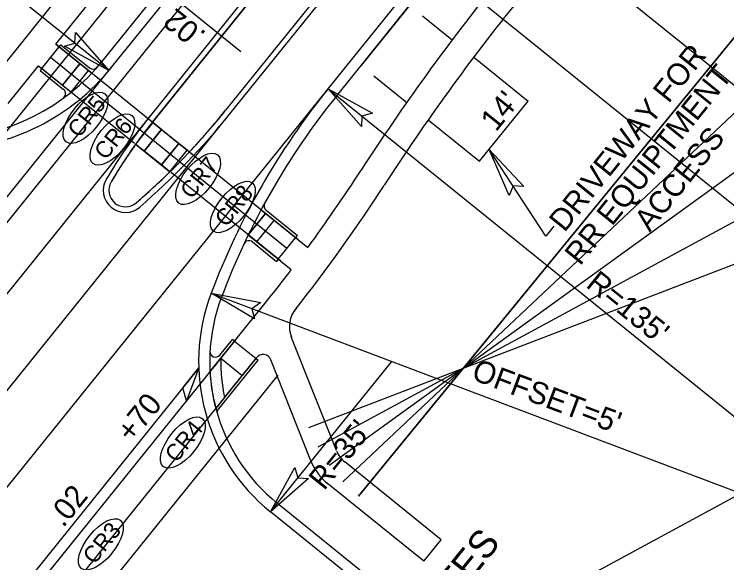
# Model space of a CAD drawing. Extents: x 1486489 to 1490134, y 497089 to 500876.
# Drawn here: x 1488715.1 to 1488844.3, y 499048.4 to 499147.7 of the extents above; entities that cross this region are included whole.
import ezdxf

# ---------------------------------------------------------------- set-up
doc = ezdxf.new("R2010")
doc.units = 0
for name, color, linetype in [('DEV PRELIMINARY STAMP CELL', 7, 'Continuous'), ('Gray Area Fill Shapes', 7, 'Continuous'), ('Pattern 5', 7, 'Continuous'), ('Prop Conc 5in Monolithic Surface Mount Island', 7, 'Continuous'), ('Prop Conc Drive Radius Type', 7, 'Continuous'), ('Prop DSN Text', 7, 'Continuous'), ('Prop Guardrail Anchor Unit CELL', 7, 'Continuous'), ('Prop Horizontal Alignment Station Label', 7, 'Continuous'), ('Prop North Arrow NAD83 for Plan Sheets CELL', 7, 'Continuous'), ('Prop Text', 7, 'Continuous'), ('Prop WCC CELL', 7, 'Continuous'), ('Scratch_Level_0', 7, 'Continuous'), ('Scratch_Level_5', 7, 'Continuous'), ('Sheet Block Title CELL', 7, 'Continuous'), ('Sheet Border Standard 30in CELL', 7, 'Continuous'), ('Sheet Cutting Line CELL', 7, 'Continuous'), ('Sheet Plan CELL', 7, 'Continuous'), ('Sheet Plot Border Outside CELL', 7, 'Continuous'), ('Sheet Sticker Exception Certification CELL', 7, 'Continuous'), ('Sheet Title CELL', 7, 'Continuous')]:
    doc.layers.add(name, color=color, linetype=linetype)

msp = doc.modelspace()

# ---------------------------------------------------------------- linework, layer by layer
at = {"layer": 'DEV PRELIMINARY STAMP CELL'}
for p, q in [((1488756.24, 499140.92), (1488743.4, 499151.27)), ((1488748.59, 499083.64), (1488718.98, 499046.92))]:
    msp.add_line(p, q, dxfattribs=at)
msp.add_lwpolyline([(1488748.59, 499083.64), (1488746.38, 499077.71), (1488745.69, 499080.04)], close=True, dxfattribs=at)
at = {"layer": 'Pattern 5'}
for p, q in [((1488727.05, 499138.76), (1488723.91, 499134.87)), ((1488728.61, 499137.51), (1488727.05, 499138.76)), ((1488725.47, 499133.61), (1488728.61, 499137.51)), ((1488723.91, 499134.87), (1488725.47, 499133.61)), ((1488740.29, 499128.08), (1488737.15, 499124.19)), ((1488741.85, 499126.83), (1488740.29, 499128.08)), ((1488738.71, 499122.94), (1488741.85, 499126.83)), ((1488737.15, 499124.19), (1488738.71, 499122.94)), ((1488744.95, 499124.33), (1488741.81, 499120.44)), ((1488746.51, 499123.07), (1488744.95, 499124.33)), ((1488743.37, 499119.18), (1488746.51, 499123.07)), ((1488741.81, 499120.44), (1488743.37, 499119.18)), ((1488760.7, 499111.63), (1488757.56, 499107.73)), ((1488762.26, 499110.37), (1488760.7, 499111.63)), ((1488759.12, 499106.48), (1488762.26, 499110.37)), ((1488757.56, 499107.73), (1488759.12, 499106.48)), ((1488750.62, 499082.97), (1488752.58, 499085.4)), ((1488751.81, 499084.16), (1488751.81, 499084.16)), ((1488752.05, 499084.45), (1488752.05, 499084.45)), ((1488752.28, 499084.74), (1488752.28, 499084.74)), ((1488752.46, 499084.36), (1488752.46, 499084.36)), ((1488752.52, 499085.03), (1488752.52, 499085.03)), ((1488750.87, 499082.99), (1488750.87, 499082.99)), ((1488751.1, 499083.28), (1488751.1, 499083.28)), ((1488751.28, 499082.9), (1488751.28, 499082.9)), ((1488751.34, 499083.57), (1488751.34, 499083.57)), ((1488751.51, 499083.19), (1488751.51, 499083.19)), ((1488751.57, 499083.87), (1488751.57, 499083.87)), ((1488751.69, 499082.81), (1488751.69, 499082.81)), ((1488751.75, 499083.48), (1488751.75, 499083.48)), ((1488751.92, 499083.1), (1488751.92, 499083.1)), ((1488751.98, 499083.78), (1488751.98, 499083.78)), ((1488752.16, 499083.39), (1488752.16, 499083.39)), ((1488752.22, 499084.07), (1488752.22, 499084.07)), ((1488752.33, 499083.01), (1488752.33, 499083.01)), ((1488752.39, 499083.69), (1488752.39, 499083.69)), ((1488752.57, 499083.31), (1488752.57, 499083.31)), ((1488750.75, 499081.64), (1488750.75, 499081.64)), ((1488750.81, 499082.32), (1488750.81, 499082.32)), ((1488750.98, 499081.93), (1488750.98, 499081.93)), ((1488751.04, 499082.61), (1488751.04, 499082.61)), ((1488751.16, 499081.55), (1488751.16, 499081.55)), ((1488751.22, 499082.23), (1488751.22, 499082.23)), ((1488751.39, 499081.85), (1488751.39, 499081.85)), ((1488751.45, 499082.52), (1488751.45, 499082.52)), ((1488751.63, 499082.14), (1488751.63, 499082.14)), ((1488751.8, 499081.76), (1488751.8, 499081.76)), ((1488751.86, 499082.43), (1488751.86, 499082.43)), ((1488752.04, 499082.05), (1488752.04, 499082.05)), ((1488752.1, 499082.72), (1488752.1, 499082.72)), ((1488752.21, 499081.67), (1488752.21, 499081.67)), ((1488752.27, 499082.34), (1488752.27, 499082.34)), ((1488752.45, 499081.96), (1488752.45, 499081.96)), ((1488752.51, 499082.63), (1488752.51, 499082.63)), ((1488752.62, 499081.58), (1488752.62, 499081.58)), ((1488750.86, 499080.59), (1488750.86, 499080.59)), ((1488750.92, 499081.26), (1488750.92, 499081.26)), ((1488751.03, 499080.21), (1488751.03, 499080.21)), ((1488751.09, 499080.88), (1488751.09, 499080.88)), ((1488751.27, 499080.5), (1488751.27, 499080.5)), ((1488751.33, 499081.17), (1488751.33, 499081.17)), ((1488751.5, 499080.79), (1488751.5, 499080.79)), ((1488751.57, 499081.46), (1488751.57, 499081.46)), ((1488751.68, 499080.41), (1488751.68, 499080.41)), ((1488751.74, 499081.08), (1488751.74, 499081.08)), ((1488751.91, 499080.7), (1488751.91, 499080.7)), ((1488751.97, 499081.37), (1488751.97, 499081.37)), ((1488752.09, 499080.32), (1488752.09, 499080.32)), ((1488752.15, 499080.99), (1488752.15, 499080.99)), ((1488752.32, 499080.61), (1488752.32, 499080.61)), ((1488752.38, 499081.29), (1488752.38, 499081.29)), ((1488752.5, 499080.23), (1488752.5, 499080.23)), ((1488752.56, 499080.9), (1488752.56, 499080.9)), ((1488752.73, 499080.52), (1488752.73, 499080.52)), ((1488751.15, 499079.15), (1488751.15, 499079.15)), ((1488751.21, 499079.83), (1488751.21, 499079.83)), ((1488751.38, 499079.44), (1488751.38, 499079.44)), ((1488751.44, 499080.12), (1488751.44, 499080.12)), ((1488751.56, 499079.06), (1488751.56, 499079.06)), ((1488751.62, 499079.74), (1488751.62, 499079.74)), ((1488751.79, 499079.35), (1488751.79, 499079.35)), ((1488751.85, 499080.03), (1488751.85, 499080.03)), ((1488751.97, 499078.97), (1488751.97, 499078.97)), ((1488752.03, 499079.65), (1488752.03, 499079.65)), ((1488752.2, 499079.27), (1488752.2, 499079.27)), ((1488752.26, 499079.94), (1488752.26, 499079.94)), ((1488752.44, 499079.56), (1488752.44, 499079.56)), ((1488752.61, 499079.18), (1488752.61, 499079.18)), ((1488752.67, 499079.85), (1488752.67, 499079.85)), ((1488752.85, 499079.47), (1488752.85, 499079.47)), ((1488752.91, 499080.14), (1488752.91, 499080.14)), ((1488753.02, 499079.09), (1488753.02, 499079.09)), ((1488751.26, 499078.1), (1488751.26, 499078.1)), ((1488751.32, 499078.77), (1488751.32, 499078.77)), ((1488751.43, 499077.72), (1488751.43, 499077.72)), ((1488751.49, 499078.39), (1488751.49, 499078.39)), ((1488751.67, 499078.01), (1488751.67, 499078.01)), ((1488753.26, 499078.28), (1488751.68, 499076.32)), ((1488751.73, 499078.68), (1488751.73, 499078.68)), ((1488751.84, 499077.63), (1488751.84, 499077.63)), ((1488751.9, 499078.3), (1488751.9, 499078.3)), ((1488752.08, 499077.92), (1488752.08, 499077.92)), ((1488752.14, 499078.59), (1488752.14, 499078.59)), ((1488752.31, 499078.21), (1488752.31, 499078.21)), ((1488752.38, 499078.88), (1488752.38, 499078.88)), ((1488752.49, 499077.83), (1488752.49, 499077.83)), ((1488752.55, 499078.5), (1488752.55, 499078.5)), ((1488752.72, 499078.12), (1488752.72, 499078.12)), ((1488752.78, 499078.79), (1488752.78, 499078.79)), ((1488752.96, 499078.41), (1488752.96, 499078.41)), ((1488751.61, 499077.34), (1488751.61, 499077.34)), ((1488751.78, 499076.95), (1488751.78, 499076.95)), ((1488752.02, 499077.25), (1488752.02, 499077.25)), ((1488752.25, 499077.54), (1488752.25, 499077.54))]:
    msp.add_line(p, q, dxfattribs=at)
for radius, start, end in [(31, 178.9, 192.1429), (33, 183.1773, 194.8995)]:
    msp.add_arc((1488783.57, 499084.8), radius, start, end, dxfattribs=at)
at = {"layer": 'Prop Conc 5in Monolithic Surface Mount Island'}
for p, q in [((1488740.18, 499128.17), (1488785.51, 499184.38)), ((1488785.51, 499184.38), (1488740.18, 499128.17)), ((1488753.47, 499130.31), (1488792.52, 499178.73)), ((1488753.47, 499130.31), (1488792.52, 499178.73)), ((1488738.71, 499122.94), (1488737.15, 499124.19)), ((1488744.95, 499124.33), (1488746.51, 499123.07)), ((1488741.81, 499120.44), (1488738.71, 499122.94)), ((1488746.51, 499123.07), (1488746.89, 499122.77)), ((1488743.37, 499119.18), (1488741.81, 499120.44))]:
    msp.add_line(p, q, dxfattribs=at)
msp.add_lwpolyline([(1488740.18, 499128.17), (1488740.29, 499128.08), (1488741.85, 499126.83), (1488744.95, 499124.33)], dxfattribs=at)
for centre, radius, start, end in [((1488653.05, 499211.29), 129, 310.743, 321.1156), ((1488653.05, 499211.29), 129, 316.6697, 321.1156), ((1488809.46, 499072.3), 89, 141.1156, 149.5986), ((1488809.46, 499072.3), 89, 144.3362, 149.5986), ((1488653.05, 499211.29), 129, 310.743, 314.4382), ((1488735.29, 499115.82), 3, 149.5986, 310.743), ((1488735.29, 499115.82), 3, 149.5986, 310.743)]:
    msp.add_arc(centre, radius, start, end, dxfattribs=at)
at = {"layer": 'Prop Conc Drive Radius Type'}
msp.add_line((1488786.78, 499149.32), (1488778, 499138.42), dxfattribs=at)
at = {"layer": 'Prop DSN Text'}
msp.add_line((1488566.47, 498943.86), (1488817.57, 499255.22), dxfattribs=at)
at = {"layer": 'Prop Horizontal Alignment Station Label'}
for p, q in [((1488710.38, 499134.95), (1488753.3, 499188.25)), ((1488722.67, 499142.3), (1488757.19, 499185.11)), ((1488722.67, 499142.3), (1488729.19, 499137.04)), ((1488720.14, 499137.91), (1488723.28, 499141.8)), ((1488714.03, 499131.55), (1488719.53, 499138.4)), ((1488719.53, 499138.4), (1488725.47, 499133.61)), ((1488723.91, 499134.87), (1488727.05, 499138.76)), ((1488725.47, 499133.61), (1488728.61, 499137.51)), ((1488740.29, 499128.09), (1488737.15, 499124.19)), ((1488740.18, 499128.17), (1488746.89, 499122.77)), ((1488741.85, 499126.83), (1488738.71, 499122.94)), ((1488737.15, 499124.19), (1488743.37, 499119.18)), ((1488741.81, 499120.44), (1488744.95, 499124.33)), ((1488743.37, 499119.18), (1488746.51, 499123.07)), ((1488757.56, 499107.73), (1488760.7, 499111.63)), ((1488759.89, 499112.28), (1488768.35, 499105.45)), ((1488759.12, 499106.48), (1488762.26, 499110.37)), ((1488757.56, 499107.73), (1488765.36, 499101.45)), ((1488763.01, 499103.34), (1488766.15, 499107.23)), ((1488750.62, 499082.97), (1488760.09, 499094.72)), ((1488773.56, 499068.66), (1488765.37, 499089.29)), ((1488755.09, 499088.51), (1488758.98, 499085.37)), ((1488752.58, 499085.4), (1488756.47, 499082.26)), ((1488753.26, 499078.28), (1488759.07, 499085.48)), ((1488768.91, 499066.82), (1488761.64, 499085.14)), ((1488792.52, 499052.53), (1488775.06, 499066.61)), ((1488789.38, 499048.64), (1488771.93, 499062.72)), ((1488789.38, 499048.64), (1488792.52, 499052.53))]:
    msp.add_line(p, q, dxfattribs=at)
for centre, radius, start, end in [((1489117.85, 498899.16), 405, 141.1156, 147.049), ((1489117.85, 498899.16), 400, 141.1156, 147.049), ((1488530.46, 499279.9), 295, 323.7475, 327.049), ((1488530.46, 499279.9), 300, 321.7531, 327.049), ((1488530.46, 499279.9), 295, 321.1156, 322.7757), ((1488770.02, 499091.14), 5, 139.2751, 201.6281), ((1488783.57, 499084.8), 31, 178.9, 192.1429), ((1488760.26, 499084.57), 1.5, 22.2994, 142.2924), ((1488778.2, 499070.5), 5, 201.6281, 231.1156), ((1488778.2, 499070.5), 10, 201.6281, 231.1156)]:
    msp.add_arc(centre, radius, start, end, dxfattribs=at)
at = {"layer": 'Prop North Arrow NAD83 for Plan Sheets CELL'}
for p, q in [((1488723.28, 499141.8), (1488723.59, 499142.19)), ((1488723.59, 499142.19), (1488728.79, 499138)), ((1488720.14, 499137.91), (1488719.83, 499137.52)), ((1488719.83, 499137.52), (1488724.07, 499134.1)), ((1488760.78, 499112.21), (1488766.46, 499107.62)), ((1488766.15, 499107.23), (1488766.46, 499107.62)), ((1488758.32, 499106.48), (1488762.7, 499102.95)), ((1488763.01, 499103.34), (1488762.7, 499102.95)), ((1488752.4, 499085.97), (1488754.7, 499088.82)), ((1488755.09, 499088.51), (1488754.7, 499088.82)), ((1488758.98, 499085.37), (1488759.37, 499085.06)), ((1488752.01, 499075.93), (1488759.37, 499085.06))]:
    msp.add_line(p, q, dxfattribs=at)
for centre, radius, start, end in [((1488729.42, 499138.78), 1, 231.1221, 318.6886), ((1488723.45, 499133.32), 1, 306.1294, 51.1156), ((1488761.41, 499112.98), 1, 151.2388, 231.1156), ((1488757.7, 499105.7), 1, 51.1156, 154.7881), ((1488751.62, 499086.6), 1, 176.7747, 321.1156), ((1488752.4, 499075.61), 0.5, 141.1156, 196.4245)]:
    msp.add_arc(centre, radius, start, end, dxfattribs=at)
at = {"layer": 'Prop Text'}
for p, q in [((1489031.06, 499369.78), (1488777.53, 499060.39)), ((1488774.7, 499063.04), (1489066.03, 499337.13)), ((1488740.1, 499128.24), (1488722.67, 499142.3)), ((1488719.75, 499138.23), (1488736.96, 499124.35)), ((1488766.54, 499106.92), (1488746.7, 499122.92)), ((1488763.4, 499103.03), (1488743.56, 499119.02)), ((1488755.33, 499088.81), (1488715.25, 499039.11)), ((1488723.04, 499032.83), (1488762.97, 499082.34))]:
    msp.add_line(p, q, dxfattribs=at)
at = {"layer": 'Prop WCC CELL'}
for centre in [(1488728.06, 499128.95), (1488732.94, 499125.01), (1488748.47, 499117.88), (1488754.77, 499112.8), (1488745.7, 499070.12), (1488730.84, 499051.69)]:
    msp.add_ellipse(centre, major_axis=(3.52, 4.36), ratio=0.462467, dxfattribs=at)
at = {"layer": 'Scratch_Level_0'}
for p, q in [((1488732.3, 499137.52), (1488701.17, 499162.63)), ((1488764.58, 499105.29), (1488721.71, 499139.86)), ((1488772.04, 499134.22), (1488877.12, 499049.47)), ((1488750.83, 499097.17), (1488877.12, 499049.47)), ((1488719.04, 499035.84), (1488758.98, 499085.37)), ((1488761.6, 499057.56), (1488783.57, 499084.8))]:
    msp.add_line(p, q, dxfattribs=at)
for points in [[(1488726.27, 499144.38), (1488732.3, 499137.52), (1488724.26, 499141.96), (1488726.15, 499142.48)], [(1488778.07, 499127.36), (1488772.04, 499134.22), (1488780.08, 499129.78), (1488778.18, 499129.26)], [(1488758.7, 499092.54), (1488750.83, 499097.17), (1488759.86, 499095.47), (1488758.22, 499094.38)], [(1488768.46, 499063.59), (1488761.6, 499057.56), (1488766.03, 499065.61), (1488766.56, 499063.71)]]:
    msp.add_lwpolyline(points, close=True, dxfattribs=at)
at = {"layer": 'Scratch_Level_5'}
for p, q in [((1488730.75, 499138.77), (1488778.25, 499197.68)), ((1488773.59, 499132.96), (1488807.05, 499174.45)), ((1488784.04, 499042.03), (1488762.85, 499059.11))]:
    msp.add_line(p, q, dxfattribs=at)
for centre, radius, start, end in [((1488701.63, 499163.2), 38, 222.6475, 321.1156), ((1488877.12, 499049.47), 133, 141.1156, 159.3105), ((1488783.57, 499084.8), 33, 159.3105, 231.1156)]:
    msp.add_arc(centre, radius, start, end, dxfattribs=at)
at = {"layer": 'Sheet Block Title CELL'}
for p, q in [((1488646.37, 499030.96), (1488732.3, 499137.52)), ((1488690.38, 499032.96), (1488772.04, 499134.22)), ((1488656.94, 499009.02), (1488754.24, 499129.68)), ((1488648.38, 499015.93), (1488739.4, 499128.8))]:
    msp.add_line(p, q, dxfattribs=at)
at = {"layer": 'Sheet Border Standard 30in CELL'}
for p, q in [((1488777.53, 499060.39), (1489031.06, 499369.78)), ((1489066.03, 499337.13), (1488774.7, 499063.04)), ((1488772.23, 499066.03), (1489096.5, 499300.23)), ((1489121.95, 499259.71), (1488770.16, 499069.32)), ((1489140.33, 499219.78), (1488788.55, 499029.37)), ((1488768.54, 499072.84), (1489141.95, 499216.25))]:
    msp.add_line(p, q, dxfattribs=at)
at = {"layer": 'Sheet Cutting Line CELL'}
for p, q in [((1488811.53, 499107.52), (1488801.22, 499123.23)), ((1488812.97, 499109.31), (1488811.53, 499107.52))]:
    msp.add_line(p, q, dxfattribs=at)
at = {"layer": 'Sheet Plan CELL'}
for p, q in [((1488632.83, 499306.48), (1488944.2, 499055.38)), ((1488933.52, 499042.15), (1488622.16, 499293.25)), ((1488574.59, 498937.3), (1488825.69, 499248.67))]:
    msp.add_line(p, q, dxfattribs=at)
at = {"layer": 'Sheet Plot Border Outside CELL'}
msp.add_lwpolyline([(1488804.86, 499114.86), (1488801.22, 499123.23), (1488807.52, 499116.54), (1488805.56, 499116.63)], close=True, dxfattribs=at)
at = {"layer": 'Sheet Sticker Exception Certification CELL'}
for p, q in [((1488732.3, 499137.52), (1488887.78, 499330.31)), ((1488772.04, 499134.22), (1488829.46, 499205.43)), ((1488739.4, 499128.8), (1488784.74, 499185.01)), ((1488754.24, 499129.68), (1488793.3, 499178.11)), ((1488789.12, 499147.44), (1488794.54, 499143.07)), ((1488798.43, 499139.93), (1488808.28, 499131.99)), ((1488780.33, 499136.54), (1488786.29, 499131.73)), ((1488799.49, 499121.09), (1488808.28, 499131.99)), ((1488790.19, 499128.59), (1488799.49, 499121.09)), ((1488782.79, 499040.47), (1488761.6, 499057.56))]:
    msp.add_line(p, q, dxfattribs=at)
for centre, radius, start, end in [((1488701.63, 499163.2), 40, 222.6475, 321.1156), ((1488877.12, 499049.47), 135, 141.1156, 159.3105), ((1488653.05, 499211.29), 130, 310.743, 321.1156), ((1488809.46, 499072.3), 90, 141.1156, 149.5986), ((1488735.29, 499115.82), 4, 149.5986, 310.743), ((1488783.57, 499084.8), 35, 159.3105, 231.1156)]:
    msp.add_arc(centre, radius, start, end, dxfattribs=at)

# ---------------------------------------------------------------- texts
at = {"layer": 'Gray Area Fill Shapes'}
for s, rotation, p in [('.02', 141.1755, (1488750.13, 499144.33)), ('+70', 51.1156, (1488736.44, 499069.95)), ('.02', 51.1156, (1488724.04, 499054.58))]:
    msp.add_text(s, height=4, rotation=rotation, dxfattribs=at).set_placement(p)
at = {"layer": 'Prop Guardrail Anchor Unit CELL'}
msp.add_text('TES', height=5, rotation=51.1156, dxfattribs=at).set_placement((1488795.27, 499041.79))
at = {"layer": 'Prop WCC CELL'}
for s, p in [('CR5', (1488726.89, 499125.14)), ('CR6', (1488731.72, 499121.15)), ('CR7', (1488747.3, 499114.07)), ('CR8', (1488753.59, 499108.99)), ('CR4', (1488744.53, 499066.31)), ('CR3', (1488729.66, 499047.88))]:
    msp.add_text(s, height=3, rotation=51.1156, dxfattribs=at).set_placement(p)
at = {"layer": 'Scratch_Level_0'}
for s, rotation, p in [("R=135'", 321.1156, (1488818.58, 499098.44)), ("OFFSET=5'", 339.3105, (1488797.82, 499081.65)), ("R=35'", 51.1156, (1488771.31, 499061.29))]:
    msp.add_text(s, height=4, rotation=rotation, dxfattribs=at).set_placement(p)
at = {"layer": 'Sheet Cutting Line CELL'}
msp.add_text("14'", height=4, rotation=51.1156, dxfattribs=at).set_placement((1488802.47, 499126.28))
at = {"layer": 'Sheet Title CELL'}
for s, p in [('DRIVEWAY FOR', (1488814.89, 499108.07)), ('RR EQUIPTMENT', (1488817.72, 499102.02)), ('ACCESS', (1488830.34, 499108.12))]:
    msp.add_text(s, height=4, rotation=51.1156, dxfattribs=at).set_placement(p)

doc.saveas('drawing.dxf')
